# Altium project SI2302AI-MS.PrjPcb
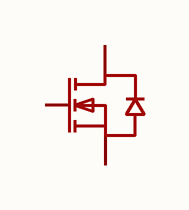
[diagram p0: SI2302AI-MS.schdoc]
1 sheet, 1 parts. Net scope: global (net labels, ports and power ports of the same name join across sheets).

## Sheet SI2302AI-MS.schdoc
size 127 x 101 mm

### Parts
Q?  si2302ai-ms  [SOT-23-3_L2.9-W1.6-P1.90-LS2.8-BR]  (value not drawn)

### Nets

Not connected (* = marked no-connect by the designer): Q? 1(G) 2(S) 3(D)

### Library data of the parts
Q? = si2302ai-ms: 数量:1个N沟道;漏源电压(Vdss):20V;连续漏极电流(Id):3A;导通电阻(RDS(on)):80mΩ@2.5V;耗散功率(Pd):800mW;阈值电压(Vgs(th)):1.2V@250uA;; Manufacturer: MSKSEMI(美森科); AddInBom: yes; ModelId: 89cb27a44ab2466697082bb9fd73a7d0; ModelName: SOT-23-3L_L2.9-W1.6-H1.1-LS2.8-P0.95; ModelTransform: 114.173,110.236,0,90,0,0,0,0,0; Number: 1个N沟道; Drain to Source Voltage: 20V; Current - Continuous Drain(Id): 3A; Pd - Power Dissipation: 800mW; Gate Charge(Qg): 5nC; Input Capacitance(Ciss): 240pF; Reverse Transfer Capacitance (Crss@Vds): 23pF; Output Capacitance(Coss): 45pF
